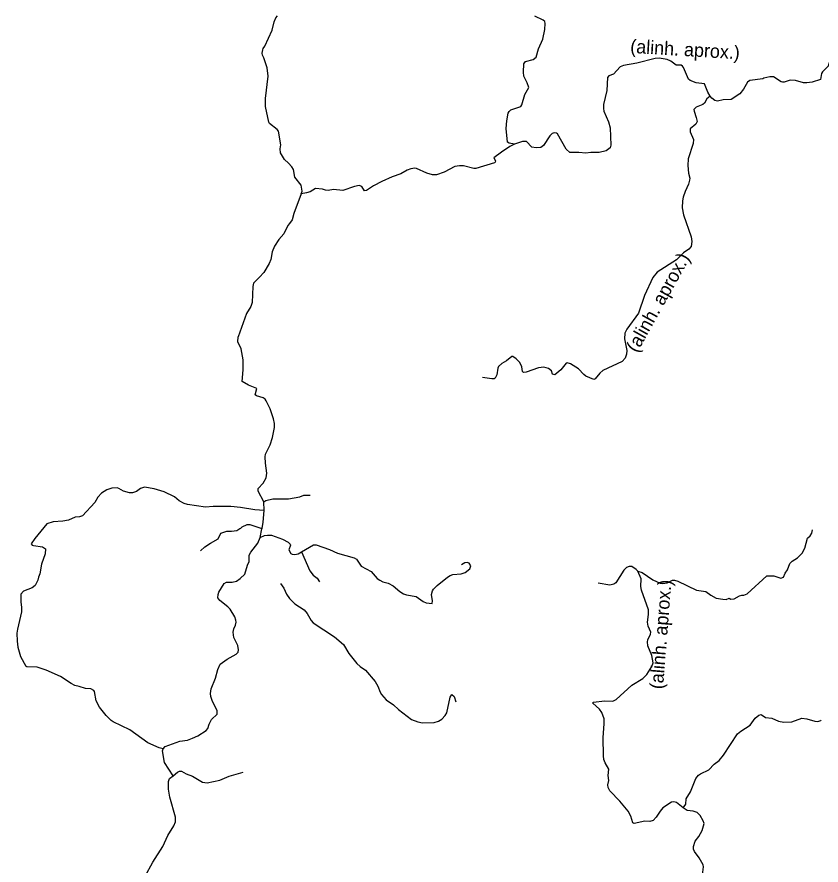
# Model space of a CAD drawing. Extents: x 332 to 501, y 9447 to 9559.
# Drawn here: x 404.96 to 427.75, y 9511.64 to 9535.67 of the extents above; entities that cross this region are included whole.
import ezdxf

# ---------------------------------------------------------------- set-up
doc = ezdxf.new("R2010")
doc.units = 0
for name, color, linetype in [('Level 31', 7, 'Continuous'), ('Level 5', 7, 'Continuous'), ('Level 6', 7, 'Continuous'), ('Level 7', 7, 'Continuous')]:
    doc.layers.add(name, color=color, linetype=linetype)

msp = doc.modelspace()

# ---------------------------------------------------------------- linework, layer by layer
at = {"layer": 'Level 5'}
for points in [[(411.9269, 9534.7388), (411.9349, 9534.7815), (411.9854, 9534.84), (412.1956, 9535.298), (412.2499, 9535.5283), (412.2963, 9535.6434), (412.3432, 9535.7039)], [(419.0647, 9532.0645), (418.9092, 9532.0977), (418.8649, 9532.1241), (418.8281, 9532.5062), (418.8441, 9532.7237), (418.884, 9532.9411), (418.908, 9532.9955), (418.9544, 9533.0355), (419.2358, 9533.1378), (419.2694, 9533.1858), (419.3557, 9533.4752), (419.4661, 9533.6703), (419.4213, 9533.803), (419.3286, 9533.9932), (419.3174, 9534.1084), (419.3254, 9534.3386), (419.3701, 9534.4106), (419.5908, 9534.4681), (419.6787, 9534.5321), (419.7427, 9534.764), (419.8626, 9535.0454), (419.917, 9535.3204), (419.9266, 9535.4835), (419.9202, 9535.5379), (419.8754, 9535.5842), (419.6324, 9535.6961)], [(428.2847, 9535.646), (428.262, 9535.557), (428.2553, 9535.1826), (428.2748, 9535.0102), (428.254, 9534.7927), (428.1485, 9534.5753), (427.9726, 9534.361), (427.9534, 9534.2731), (427.7871, 9534.1196), (427.7615, 9534.0716), (427.7343, 9533.9005), (427.4929, 9533.8237), (427.349, 9533.8062), (427.2531, 9533.8078), (427.0212, 9533.8669), (426.8693, 9533.8813), (426.7062, 9533.8221), (426.6519, 9533.8221), (426.6167, 9533.8317), (426.4008, 9533.9756), (426.2937, 9533.9756), (426.1306, 9533.9405)], [(412.0062, 9533.3612), (412.0802, 9533.9954), (412.0485, 9534.2299), (411.9589, 9534.5097), (411.9171, 9534.5839), (411.9093, 9534.6456), (411.9269, 9534.7388)], [(424.6044, 9533.4309), (424.5372, 9533.5372), (424.4485, 9533.7742), (424.2054, 9533.8094), (424.0353, 9533.8751), (423.9961, 9533.9105), (423.8536, 9534.2363), (423.8185, 9534.2779), (423.7865, 9534.3018), (423.6394, 9534.3066), (423.4907, 9534.4186), (423.39, 9534.4617), (423.1597, 9534.5017), (423.0446, 9534.4985), (422.5265, 9534.361), (422.1449, 9534.2952), (422.0511, 9534.2584), (421.8613, 9534.0476), (421.7302, 9534.0028), (421.6914, 9533.9563), (421.6793, 9533.5832), (421.5834, 9533.1875), (421.5847, 9533.0786), (421.595, 9533.0005), (421.7238, 9532.6997), (421.7734, 9532.5318), (421.7878, 9532.0425), (421.7697, 9531.9653), (421.7363, 9531.9339), (421.6535, 9531.8746), (421.4616, 9531.833), (421.2218, 9531.8298), (421.0778, 9531.809), (420.886, 9531.8282), (420.6317, 9531.8298), (420.5285, 9531.9234), (420.2767, 9532.3575), (420.2544, 9532.3783), (420.1824, 9532.3879), (420.1296, 9532.3719), (420.0641, 9532.3015), (419.8834, 9532.0313), (419.8055, 9531.976), (419.6784, 9531.9588), (419.5532, 9531.9858), (419.4005, 9532.14), (419.287, 9532.1384), (419.0647, 9532.0645)], [(426.1306, 9533.9405), (426.0954, 9533.9197), (425.734, 9533.8717), (425.6621, 9533.8253), (425.5502, 9533.6271), (425.4472, 9533.4952), (425.1984, 9533.3361), (424.9729, 9533.3249), (424.8098, 9533.2897), (424.7347, 9533.3025), (424.6506, 9533.367), (424.6044, 9533.4309)], [(413.0183, 9530.6625), (413.0424, 9530.7347), (413.0121, 9530.9077), (412.8336, 9531.1279), (412.7936, 9531.347), (412.7488, 9531.4253), (412.6577, 9531.5324), (412.5409, 9531.6316), (412.429, 9531.8174), (412.4178, 9531.9328), (412.4341, 9532.0444), (412.373, 9532.4327), (412.3363, 9532.4854), (412.1183, 9532.6535), (412.1006, 9532.6928), (412.0085, 9533.1362), (412.0062, 9533.3612)], [(424.6044, 9533.4309), (424.5116, 9533.3557), (424.4469, 9533.2321), (424.3941, 9533.1906), (424.2086, 9533.117), (424.1463, 9533.0515), (424.1479, 9533.0019), (424.2118, 9532.8196), (424.2342, 9532.7045), (424.199, 9532.6293), (424.0391, 9532.4982), (424.0359, 9532.4199), (424.1303, 9532.1992), (424.1239, 9532.0905), (423.9858, 9531.6547), (423.9738, 9531.4664), (423.9882, 9531.2469), (424.0263, 9531.1023), (424.0231, 9531.0479), (423.996, 9530.9328), (423.8967, 9530.7235), (423.8409, 9530.5651), (423.8187, 9530.4623), (423.8153, 9530.2645), (423.8501, 9530.0604), (424.0647, 9529.4458), (424.0871, 9529.311), (424.0631, 9529.1683), (424.004, 9529.0956), (423.8506, 9528.9846), (423.6474, 9528.7918), (423.1064, 9528.4432), (422.9806, 9528.2849), (422.7472, 9527.7812), (422.5761, 9527.2776), (422.2483, 9526.8283), (422.1875, 9526.7147), (422.1779, 9526.5516), (422.2451, 9526.2255), (422.2307, 9526.1167), (422.1939, 9526.008), (422.1124, 9525.9121), (421.5639, 9525.6546), (421.4792, 9525.5827), (421.3481, 9525.4148), (421.3081, 9525.4036), (421.081, 9525.4979), (421.0219, 9525.5395), (420.87, 9525.7042), (420.6477, 9525.8401), (420.555, 9525.8705), (420.5246, 9525.8593), (420.3743, 9525.677), (420.2068, 9525.5346), (420.137, 9525.5474), (420.1071, 9525.6423), (420.0222, 9525.7145), (419.8931, 9525.7484), (419.7443, 9525.733), (419.3952, 9525.6096), (419.3152, 9525.5993)], [(419.0647, 9532.0645), (418.9321, 9532.0026), (418.6945, 9531.8391)], [(418.478, 9531.6771), (418.5194, 9531.5967), (418.514, 9531.5598), (418.4895, 9531.5372), (417.9631, 9531.3805), (417.9087, 9531.3789), (417.6113, 9531.4509), (417.5026, 9531.4525), (417.3735, 9531.4304), (417.0644, 9531.275), (416.847, 9531.1966), (416.7382, 9531.1966), (416.5752, 9531.2414), (416.2873, 9531.3805), (416.233, 9531.3869), (416.1242, 9531.3693), (416.0155, 9531.3262), (415.8428, 9531.2249), (415.5934, 9531.1375), (415.2992, 9531.0048), (415.0689, 9530.8832), (414.865, 9530.7503), (414.8086, 9530.7479), (414.7384, 9530.8712), (414.654, 9530.8929), (414.5259, 9530.8698), (414.1938, 9530.7572), (413.9305, 9530.7793), (413.777, 9530.7585), (413.7018, 9530.7649), (413.6235, 9530.7953), (413.4188, 9530.8065), (413.2685, 9530.7201), (413.1661, 9530.6834), (413.0183, 9530.6625)], [(418.6945, 9531.8391), (418.478, 9531.6771)], [(413.0183, 9530.6625), (412.8048, 9530.0982), (412.7568, 9529.9255), (412.6849, 9529.8228)], [(412.6849, 9529.8228), (412.6369, 9529.7624), (412.5249, 9529.5257), (412.381, 9529.3674), (412.2579, 9529.1772), (412.1892, 9529.0141), (412.1524, 9528.7966), (412.1108, 9528.6879), (411.9589, 9528.4304), (411.8346, 9528.2999)], [(411.8346, 9528.2999), (411.6631, 9528.125), (411.6423, 9528.0355), (411.6295, 9527.5782), (411.5896, 9527.4695), (411.4614, 9527.2655), (411.2286, 9526.611)], [(419.2118, 9525.8849), (419.1111, 9525.9856), (419.0104, 9526.0528), (418.9848, 9526.0512), (418.8361, 9525.9264), (418.705, 9525.8561), (418.6042, 9525.7681), (418.5834, 9525.7218), (418.5611, 9525.5283), (418.5163, 9525.4388), (418.4875, 9525.4212), (418.4204, 9525.4212), (418.1554, 9525.4537)], [(419.3152, 9525.5993), (419.2897, 9525.6229), (419.271, 9525.757), (419.2118, 9525.8849)], [(422.5557, 9519.9646), (422.508, 9520.0182), (422.3858, 9520.0981), (422.3123, 9520.1045), (422.2387, 9520.0725), (422.1572, 9520.0006), (421.931, 9519.6366), (421.8773, 9519.6008), (421.7622, 9519.5704), (421.4313, 9519.6245)], [(422.923, 9518.2369), (422.8463, 9518.4128), (422.8319, 9518.5215), (422.8623, 9518.739), (422.8559, 9518.8749), (422.664, 9519.4297), (422.6448, 9519.5385), (422.6512, 9519.7559), (422.5557, 9519.9646)], [(421.2825, 9516.227), (421.2873, 9516.2606), (421.6183, 9516.2909), (421.8486, 9516.2862), (421.9429, 9516.3325), (422.3901, 9516.7351), (422.696, 9516.9273), (422.8127, 9517.0457), (422.955, 9517.2647), (422.9934, 9517.3735), (422.9486, 9517.5749), (422.8367, 9517.8564), (422.8287, 9517.9651), (422.8399, 9518.0194), (422.9151, 9518.1825), (422.923, 9518.2369)], [(423.8441, 9513.2651), (423.6522, 9513.416), (423.5754, 9513.4288), (423.5051, 9513.4208), (423.2668, 9513.2609), (423.1853, 9513.173), (423.0766, 9512.9987), (422.987, 9512.9091), (422.8975, 9512.8803), (422.7536, 9512.8851), (422.4498, 9512.8228), (422.4114, 9512.842), (422.3602, 9513.0243), (422.2771, 9513.1682), (422.0484, 9513.4544), (421.7654, 9513.7406), (421.7142, 9513.8429), (421.7046, 9513.9181), (421.7334, 9514.0348), (421.719, 9514.1787), (421.7334, 9514.3562), (421.6263, 9514.5337), (421.5911, 9514.636), (421.5799, 9514.732), (421.5687, 9515.2596), (421.6039, 9515.6434), (421.5975, 9515.7873), (421.5352, 9515.968), (421.468, 9516.0575), (421.2825, 9516.227)], [(423.8441, 9513.2651), (423.9176, 9513.3648), (423.924, 9513.5169), (424.0519, 9513.715), (424.2006, 9514.0924), (424.279, 9514.1899), (424.3317, 9514.2299), (424.57, 9514.3418), (424.7203, 9514.5001), (424.8562, 9514.6056), (424.9825, 9514.7544), (425.3791, 9515.3556), (425.4718, 9515.4339), (425.7436, 9515.6066), (425.8843, 9515.8081), (425.9851, 9515.8896), (426.0506, 9515.9056), (426.177, 9515.8193), (426.3544, 9515.8017), (426.5463, 9515.7185), (426.6902, 9515.6897), (426.9205, 9515.6961), (427.2051, 9515.8033), (427.3458, 9515.7889), (427.5697, 9515.7201), (427.6592, 9515.7089), (427.7438, 9515.7339)], [(427.7438, 9515.7339), (427.7516, 9515.7433)], [(424.1761, 9510.8452), (424.3493, 9511.1855), (424.3781, 9511.2878), (424.4181, 9511.5948), (424.4069, 9511.646), (424.2982, 9511.8474), (424.1611, 9512.0285), (424.1351, 9512.0889), (424.1351, 9512.1688), (424.183, 9512.3223), (424.2886, 9512.4518), (424.3749, 9512.6245), (424.4309, 9512.818), (424.4069, 9512.8947), (424.3189, 9513.0435), (424.2342, 9513.1314), (424.1255, 9513.1682), (423.9512, 9513.1906), (423.8441, 9513.2651)]]:
    msp.add_lwpolyline(points, dxfattribs=at)
at = {"layer": 'Level 6'}
for points in [[(411.3449, 9525.3425), (411.3689, 9525.669), (411.3705, 9525.9536), (411.3161, 9526.2638), (411.2154, 9526.4685), (411.2286, 9526.611)], [(412.0256, 9524.7964), (411.9919, 9524.8439), (411.9359, 9524.8754), (411.7484, 9524.9324), (411.7145, 9524.9624), (411.7559, 9525.143), (411.5256, 9525.2357), (411.3449, 9525.3425)], [(411.9589, 9521.934), (411.799, 9522.2343), (411.8006, 9522.3095), (411.9421, 9522.4619), (412.0267, 9522.6142), (412.0389, 9522.746), (412.0005, 9523.0242), (411.9925, 9523.2129), (412.0053, 9523.2801), (412.1332, 9523.5455), (412.2068, 9523.7565), (412.2555, 9524.0403), (412.2579, 9524.1483), (412.2292, 9524.2858), (412.1396, 9524.5672), (412.0256, 9524.7964)], [(411.9623, 9521.6885), (411.9589, 9521.934)], [(411.9047, 9521.1787), (411.9406, 9521.3575), (411.9623, 9521.6885)], [(410.1638, 9520.5494), (410.2811, 9520.6615), (410.4442, 9520.7583), (410.6582, 9520.8806), (410.7347, 9521.0488), (410.9079, 9521.0998), (411.0405, 9521.1049), (411.1882, 9521.1253), (411.28, 9521.1762), (411.302, 9521.1894), (411.3462, 9521.2272), (411.4838, 9521.2934), (411.4852, 9521.294)], [(411.4852, 9521.294), (411.5603, 9521.2883), (411.9039, 9521.1744)], [(411.8532, 9520.9217), (411.9021, 9521.1702)], [(411.9021, 9521.1702), (411.9047, 9521.1787)], [(411.9039, 9521.1744), (411.9047, 9521.1787)]]:
    msp.add_lwpolyline(points, dxfattribs=at)
at = {"layer": 'Level 7'}
for points in [[(411.9623, 9521.6885), (411.6983, 9521.7083), (411.2954, 9521.7738), (411.0225, 9521.8001), (410.5199, 9521.7994), (410.3008, 9521.7786), (409.7955, 9521.8538), (409.6948, 9521.8826), (409.5605, 9521.9657), (409.4278, 9522.076), (409.1322, 9522.2138), (408.8515, 9522.2984), (408.5786, 9522.3446), (408.462, 9522.3079), (408.3437, 9522.2279), (408.2349, 9522.1928), (408.1534, 9522.1848), (407.9807, 9522.2311), (407.8432, 9522.3143), (407.8, 9522.3255), (407.6497, 9522.3175), (407.509, 9522.2727), (407.3571, 9522.1768), (407.2564, 9522.0616), (407.1716, 9521.9145), (406.8166, 9521.5388), (406.7367, 9521.5068), (406.6141, 9521.5027), (406.4249, 9521.4093), (406.265, 9521.3837), (405.99, 9521.3709), (405.8093, 9521.3133), (405.4655, 9520.8912), (405.3664, 9520.7409), (405.3888, 9520.7089), (405.4255, 9520.6945), (405.6798, 9520.6545), (405.7677, 9520.605), (405.7629, 9520.4579), (405.6574, 9520.1637), (405.6085, 9519.8952), (405.5678, 9519.7991), (405.5503, 9519.7096), (405.4783, 9519.5656), (405.3873, 9519.4983), (405.1457, 9519.3978), (405.0738, 9519.3194), (405.0658, 9519.1035), (405.0882, 9518.9373), (405.085, 9518.8189), (404.9714, 9518.3233), (404.9602, 9518.2113), (404.9698, 9517.9811), (404.9858, 9517.8148), (405.0594, 9517.5525), (405.2092, 9517.2812)], [(411.9589, 9521.934), (412.0144, 9521.9696), (412.21, 9522.0137), (412.6577, 9522.0169), (412.9775, 9522.0776), (413.0942, 9522.1176), (413.2701, 9522.1192)], [(422.5557, 9519.9646), (422.68, 9519.9318), (422.979, 9519.7208), (423.1885, 9519.6264), (423.2556, 9519.6184), (423.3868, 9519.6376), (423.5403, 9519.7096), (423.5978, 9519.7144), (423.6874, 9519.6872), (424.2198, 9519.4281), (424.4805, 9519.3898), (424.6244, 9519.2858), (424.7715, 9519.2059), (424.9601, 9519.1723), (425.0561, 9519.1707), (425.1472, 9519.1995), (425.1949, 9519.1764), (425.2895, 9519.1835), (425.435, 9519.2666), (425.5054, 9519.2922), (425.5614, 9519.289), (425.6541, 9519.329), (426.2085, 9519.836), (426.4084, 9519.8355), (426.6103, 9519.7719), (426.6854, 9519.8007), (426.727, 9519.9126), (426.7972, 9520.0109), (426.8677, 9520.186), (426.9253, 9520.2564), (427.0852, 9520.3491), (427.2115, 9520.4803), (427.2866, 9520.6162), (427.3682, 9520.9008), (427.4401, 9520.9727), (427.4849, 9521.0479), (427.5085, 9521.1377)], [(409.101, 9514.9397), (409.1639, 9515.0009), (409.5781, 9515.1509), (409.7907, 9515.1813), (409.933, 9515.234), (410.0849, 9515.3076), (410.3232, 9515.4547), (410.3695, 9515.5139), (410.4063, 9515.6338), (410.4719, 9515.7681), (410.6334, 9515.9136), (410.63, 9516.0242), (410.5055, 9516.2718), (410.4543, 9516.4173), (410.4431, 9516.5052), (410.4607, 9516.6315), (410.5854, 9516.9353), (410.6558, 9517.1784), (410.7213, 9517.3319), (410.9164, 9517.4742), (411.169, 9517.6181), (411.2298, 9517.6693), (411.241, 9517.7364), (411.2154, 9517.8627), (411.1099, 9518.093), (411.0859, 9518.2369), (411.1035, 9518.3312), (411.1578, 9518.4416), (411.1738, 9518.5279), (411.1674, 9518.5823), (411.1307, 9518.6782), (411.0059, 9518.8909), (410.9404, 9518.9612), (410.7101, 9519.1403), (410.651, 9519.2139), (410.659, 9519.3082), (410.6782, 9519.377), (410.8348, 9519.6232), (410.8972, 9519.6552), (411.0603, 9519.6536), (411.1802, 9519.6872), (411.2874, 9519.7575), (411.4217, 9519.887), (411.4918, 9520.1415), (411.5384, 9520.242), (411.5448, 9520.4195), (411.5848, 9520.5058), (411.7869, 9520.7653), (411.8532, 9520.9217)], [(411.8532, 9520.9217), (411.9774, 9520.9796), (412.0634, 9520.9929), (412.1719, 9520.9865), (412.485, 9520.8736), (412.6415, 9520.7943), (412.702, 9520.7359), (412.7088, 9520.7084), (412.6673, 9520.573), (412.7216, 9520.4707), (412.7584, 9520.4515), (412.8368, 9520.4435), (412.9279, 9520.4627), (413.0284, 9520.5209)], [(413.0284, 9520.5209), (413.3627, 9520.7145), (413.4403, 9520.7165), (413.8217, 9520.5794), (414.0424, 9520.4803), (414.5125, 9520.3507), (414.5796, 9520.306), (414.7187, 9520.1061), (414.997, 9519.956), (415.1729, 9519.7639), (415.248, 9519.7112), (415.3312, 9519.6696), (415.4831, 9519.6248), (415.6174, 9519.5577), (415.8092, 9519.3962), (415.918, 9519.3306), (416.001, 9519.2977), (416.2745, 9519.2507), (416.4728, 9519.1099), (416.5528, 9519.07), (416.7267, 9519.0551)], [(413.0284, 9520.5209), (413.2568, 9519.9743), (413.3585, 9519.8529), (413.4641, 9519.7717), (413.5373, 9519.6651)], [(416.7267, 9519.0551), (416.7366, 9519.1251), (416.7063, 9519.3034), (416.7334, 9519.4074), (416.7606, 9519.4585), (416.8646, 9519.5625), (417.162, 9519.7991), (417.2387, 9519.8439), (417.3155, 9519.8727), (417.5473, 9519.8934), (417.6624, 9519.9334), (417.7952, 9520.0357), (417.8191, 9520.1221), (417.7792, 9520.194), (417.7152, 9520.2164), (417.6561, 9520.202), (417.5565, 9520.1474)], [(412.426, 9519.6183), (412.5268, 9519.4825), (412.602, 9519.3194), (412.6867, 9519.1931), (412.8354, 9519.0476), (413.0977, 9518.8701), (413.184, 9518.7726), (413.2991, 9518.5679), (413.3519, 9518.5023), (413.9627, 9518.109), (414.2169, 9517.8883), (414.3656, 9517.6341), (414.5879, 9517.3511), (414.6822, 9517.2647), (414.8373, 9517.1592), (415.114, 9516.8474), (415.1907, 9516.7131), (415.2515, 9516.5404), (415.2918, 9516.472)], [(406.7193, 9516.7004), (406.6024, 9516.7339), (406.4984, 9516.785), (406.1898, 9516.9833), (405.7885, 9517.1672), (405.5359, 9517.2535), (405.2417, 9517.2615), (405.2092, 9517.2812)], [(409.101, 9514.9397), (408.9949, 9514.9656), (408.673, 9515.1061), (408.1582, 9515.4723), (407.6865, 9515.6961), (407.6257, 9515.7409), (407.4898, 9515.8784), (407.2963, 9516.1151), (407.2052, 9516.2974), (407.1588, 9516.5564), (407.1396, 9516.5916), (407.0501, 9516.6379), (406.8982, 9516.6491), (406.7193, 9516.7004)], [(415.2918, 9516.472), (415.4258, 9516.3229), (415.6304, 9516.1806), (415.7743, 9516.0456), (416.143, 9515.764), (416.3164, 9515.6961), (416.4507, 9515.6674), (416.7801, 9515.6817), (416.908, 9515.7153), (417.0023, 9515.7729), (417.0951, 9515.8768), (417.1415, 9515.9552), (417.2406, 9516.3965), (417.2838, 9516.4764), (417.3509, 9516.4157), (417.3972, 9516.2696)], [(409.3824, 9514.1681), (409.1431, 9514.5449), (409.0888, 9514.8759), (409.101, 9514.9397)], [(408.6955, 9510.5807), (408.6665, 9510.623), (408.6475, 9510.7186), (408.6475, 9510.9312), (408.5931, 9511.2078), (408.5931, 9511.3294), (408.8074, 9511.7259), (409.092, 9512.172), (409.2391, 9512.479), (409.4102, 9512.7524), (409.4501, 9512.8676), (409.4533, 9512.9971), (409.2902, 9513.5663), (409.2551, 9513.7934), (409.2551, 9514.006), (409.2807, 9514.0908), (409.3824, 9514.1681)], [(409.3824, 9514.1681), (409.5109, 9514.2731), (409.5637, 9514.2986), (409.626, 9514.3018), (409.7571, 9514.2251), (409.933, 9514.1595), (410.2208, 9513.99), (410.3488, 9513.9677), (410.7085, 9514.046), (410.974, 9514.1595), (411.3705, 9514.2715)]]:
    msp.add_lwpolyline(points, dxfattribs=at)

# ---------------------------------------------------------------- texts
at = {"layer": 'Level 31'}
for rotation, p in [(356.61373, (422.3333, 9534.6554)), (60.88318, (422.5334, 9526.1359)), (85.44262, (423.2663, 9516.6154))]:
    msp.add_text('(alinh. aprox.)', height=0.38, rotation=rotation, dxfattribs=at).set_placement(p)

doc.saveas('drawing.dxf')
